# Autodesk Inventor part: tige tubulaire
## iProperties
Created: 2002-06
Part Number: tige tubulaire
Material: Par défaut
Document SubType Name: Modélisation
Designer: REVEST Pierre
Control State: 0
Master: False
Checked Out: False
Shininess: 43.0
Length Units: 11269
Angle Units: 11279
Time Units: 11290
Mass Units: 11283
Length Display Precision: 3
Angle Display Precision: 2
Density: 0.0
Volumn: 0.0
Area: 0.0
PropertySet Name: Model Information
Author: REVEST Pierre
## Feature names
1. Extrusion1
2. Extrusion3
